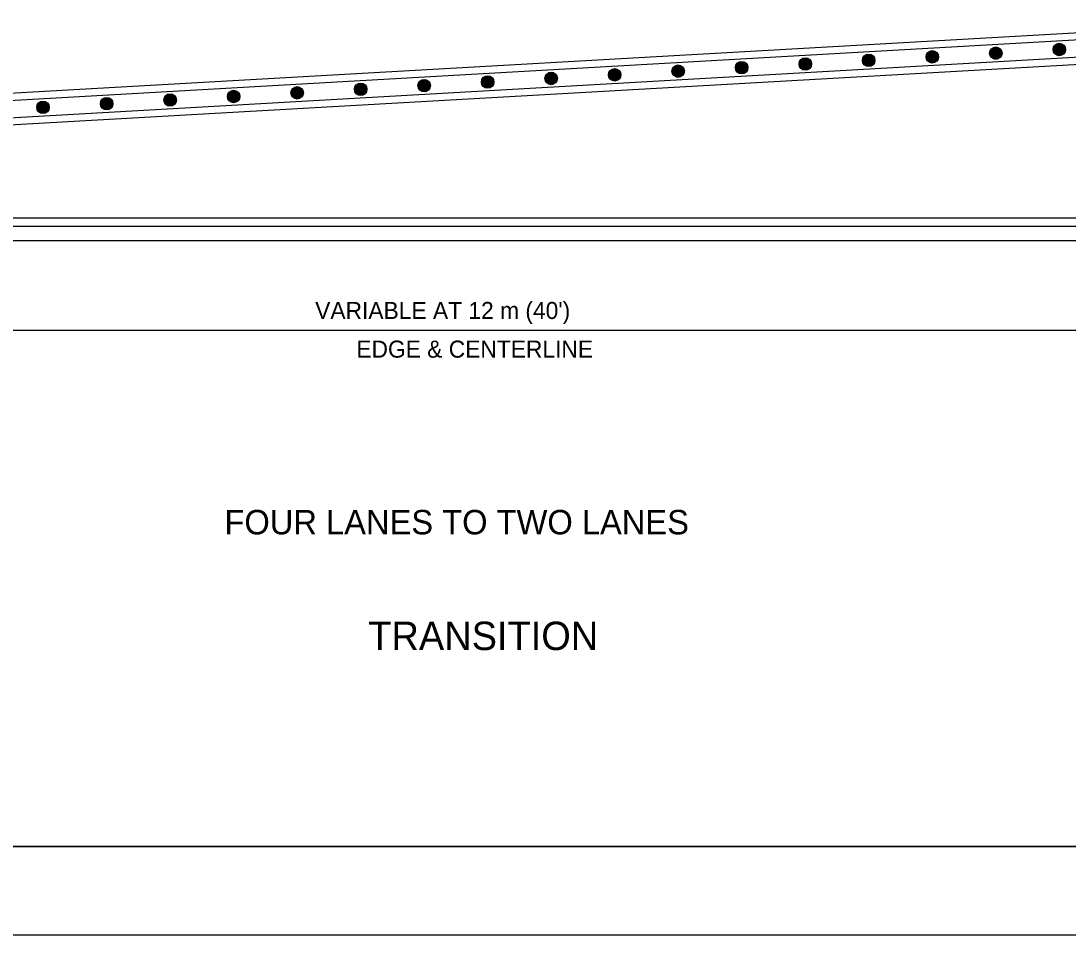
# Model space of a CAD drawing. Extents: x 639362 to 641108, y 298458 to 299646.
# Drawn here: x 639604.4 to 639788.7, y 298457.6 to 298618.5 of the extents above; entities that cross this region are included whole.
import ezdxf

# ---------------------------------------------------------------- set-up
doc = ezdxf.new("R2010")
doc.units = 0
for name, color, linetype in [('1', 7, 'Continuous'), ('2', 7, 'Continuous'), ('PLT-BNDY', 7, 'Continuous')]:
    doc.layers.add(name, color=color, linetype=linetype)

msp = doc.modelspace()

# ---------------------------------------------------------------- linework, layer by layer
at = {"layer": '1'}
for p, q in [((640189.27, 298473.19), (639403.27, 298473.19)), ((639403.27, 298473.19), (639989.27, 298473.19))]:
    msp.add_line(p, q, dxfattribs=at)
at = {"layer": '2'}
for p, q in [((639797.98, 298616.83), (639585.9, 298604.78)), ((639585.93, 298603.58), (639798.02, 298615.63)), ((639797.98, 298612.52), (639585.9, 298600.47)), ((639585.93, 298599.27), (639798.02, 298611.32)), ((639431.63, 298583.85), (639951.12, 298583.85)), ((639431.63, 298582.35), (639951.12, 298582.35)), ((639431.63, 298579.85), (639951.12, 298579.85)), ((639798, 298564.02), (639585.52, 298564.02))]:
    msp.add_line(p, q, dxfattribs=at)
for centre, radius in [((639776.02, 298612.82), 1.1), ((639776.02, 298612.82), 1.02), ((639787.2, 298613.46), 1.1), ((639787.2, 298613.46), 1.02), ((639787.2, 298613.46), 0.946), ((639787.2, 298613.46), 0.868), ((639787.2, 298613.46), 0.789), ((639787.2, 298613.46), 0.711), ((639787.2, 298613.46), 0.633), ((639787.2, 298613.46), 0.554), ((639787.2, 298613.46), 0.476), ((639787.2, 298613.46), 0.398), ((639787.2, 298613.46), 0.32), ((639742.47, 298610.92), 1.1), ((639742.47, 298610.92), 1.02), ((639753.65, 298611.55), 1.1), ((639753.65, 298611.55), 1.02), ((639753.65, 298611.55), 0.946), ((639753.65, 298611.55), 0.868), ((639753.65, 298611.55), 0.789), ((639753.65, 298611.55), 0.711), ((639753.65, 298611.55), 0.633), ((639753.65, 298611.55), 0.554), ((639753.65, 298611.55), 0.476), ((639753.65, 298611.55), 0.398), ((639764.84, 298612.19), 1.1), ((639764.84, 298612.19), 1.02), ((639764.84, 298612.19), 0.946), ((639764.84, 298612.19), 0.868), ((639764.84, 298612.19), 0.789), ((639764.84, 298612.19), 0.711), ((639764.84, 298612.19), 0.633), ((639764.84, 298612.19), 0.554), ((639764.84, 298612.19), 0.476), ((639764.84, 298612.19), 0.398), ((639764.84, 298612.19), 0.32), ((639764.84, 298612.19), 0.241), ((639764.84, 298612.19), 0.163), ((639764.84, 298612.19), 0.0846), ((639776.02, 298612.82), 0.946), ((639776.02, 298612.82), 0.868), ((639776.02, 298612.82), 0.789), ((639776.02, 298612.82), 0.711), ((639776.02, 298612.82), 0.633), ((639776.02, 298612.82), 0.554), ((639776.02, 298612.82), 0.476), ((639776.02, 298612.82), 0.398), ((639776.02, 298612.82), 0.32), ((639776.02, 298612.82), 0.241), ((639776.02, 298612.82), 0.163), ((639776.02, 298612.82), 0.0846), ((639787.2, 298613.46), 0.241), ((639787.2, 298613.46), 0.163), ((639787.2, 298613.46), 0.0846), ((639708.92, 298609.01), 1.1), ((639720.1, 298609.65), 1.1), ((639720.1, 298609.65), 1.02), ((639720.1, 298609.65), 0.946), ((639720.1, 298609.65), 0.868), ((639720.1, 298609.65), 0.789), ((639720.1, 298609.65), 0.711), ((639720.1, 298609.65), 0.633), ((639720.1, 298609.65), 0.554), ((639720.1, 298609.65), 0.476), ((639731.28, 298610.28), 1.1), ((639731.28, 298610.28), 1.02), ((639731.28, 298610.28), 0.946), ((639731.28, 298610.28), 0.868), ((639731.28, 298610.28), 0.789), ((639731.28, 298610.28), 0.711), ((639731.28, 298610.28), 0.633), ((639731.28, 298610.28), 0.554), ((639731.28, 298610.28), 0.476), ((639731.28, 298610.28), 0.398), ((639731.28, 298610.28), 0.32), ((639731.28, 298610.28), 0.241), ((639731.28, 298610.28), 0.163), ((639731.28, 298610.28), 0.0846), ((639742.47, 298610.92), 0.946), ((639742.47, 298610.92), 0.868), ((639742.47, 298610.92), 0.789), ((639742.47, 298610.92), 0.711), ((639742.47, 298610.92), 0.633), ((639742.47, 298610.92), 0.554), ((639742.47, 298610.92), 0.476), ((639742.47, 298610.92), 0.398), ((639742.47, 298610.92), 0.32), ((639742.47, 298610.92), 0.241), ((639742.47, 298610.92), 0.163), ((639742.47, 298610.92), 0.0846), ((639753.65, 298611.55), 0.32), ((639753.65, 298611.55), 0.241), ((639753.65, 298611.55), 0.163), ((639753.65, 298611.55), 0.0846), ((639686.55, 298607.74), 1.1), ((639686.55, 298607.74), 1.02), ((639686.55, 298607.74), 0.946), ((639686.55, 298607.74), 0.868), ((639686.55, 298607.74), 0.789), ((639686.55, 298607.74), 0.711), ((639686.55, 298607.74), 0.633), ((639686.55, 298607.74), 0.554), ((639697.73, 298608.38), 1.1), ((639697.73, 298608.38), 1.02), ((639697.73, 298608.38), 0.946), ((639697.73, 298608.38), 0.868), ((639697.73, 298608.38), 0.789), ((639697.73, 298608.38), 0.711), ((639697.73, 298608.38), 0.633), ((639697.73, 298608.38), 0.554), ((639697.73, 298608.38), 0.476), ((639697.73, 298608.38), 0.398), ((639697.73, 298608.38), 0.32), ((639697.73, 298608.38), 0.241), ((639697.73, 298608.38), 0.163), ((639697.73, 298608.38), 0.0846), ((639708.92, 298609.01), 1.02), ((639708.92, 298609.01), 0.946), ((639708.92, 298609.01), 0.868), ((639708.92, 298609.01), 0.789), ((639708.92, 298609.01), 0.711), ((639708.92, 298609.01), 0.633), ((639708.92, 298609.01), 0.554), ((639708.92, 298609.01), 0.476), ((639708.92, 298609.01), 0.398), ((639708.92, 298609.01), 0.32), ((639708.92, 298609.01), 0.241), ((639708.92, 298609.01), 0.163), ((639708.92, 298609.01), 0.0846), ((639720.1, 298609.65), 0.398), ((639720.1, 298609.65), 0.32), ((639720.1, 298609.65), 0.241), ((639720.1, 298609.65), 0.163), ((639720.1, 298609.65), 0.0846), ((639653, 298605.84), 1.1), ((639653, 298605.84), 1.02), ((639653, 298605.84), 0.946), ((639653, 298605.84), 0.868), ((639653, 298605.84), 0.789), ((639653, 298605.84), 0.711), ((639653, 298605.84), 0.633), ((639664.18, 298606.47), 1.1), ((639664.18, 298606.47), 1.02), ((639664.18, 298606.47), 0.946), ((639664.18, 298606.47), 0.868), ((639664.18, 298606.47), 0.789), ((639664.18, 298606.47), 0.711), ((639664.18, 298606.47), 0.633), ((639664.18, 298606.47), 0.554), ((639664.18, 298606.47), 0.476), ((639664.18, 298606.47), 0.398), ((639664.18, 298606.47), 0.32), ((639664.18, 298606.47), 0.241), ((639664.18, 298606.47), 0.163), ((639664.18, 298606.47), 0.0846), ((639675.37, 298607.11), 1.1), ((639675.37, 298607.11), 1.02), ((639675.37, 298607.11), 0.946), ((639675.37, 298607.11), 0.868), ((639675.37, 298607.11), 0.789), ((639675.37, 298607.11), 0.711), ((639675.37, 298607.11), 0.633), ((639675.37, 298607.11), 0.554), ((639675.37, 298607.11), 0.476), ((639675.37, 298607.11), 0.398), ((639675.37, 298607.11), 0.32), ((639675.37, 298607.11), 0.241), ((639675.37, 298607.11), 0.163), ((639675.37, 298607.11), 0.0846), ((639686.55, 298607.74), 0.476), ((639686.55, 298607.74), 0.398), ((639686.55, 298607.74), 0.32), ((639686.55, 298607.74), 0.241), ((639686.55, 298607.74), 0.163), ((639686.55, 298607.74), 0.0846), ((639619.45, 298603.93), 1.1), ((639619.45, 298603.93), 1.02), ((639619.45, 298603.93), 0.946), ((639619.45, 298603.93), 0.868), ((639619.45, 298603.93), 0.789), ((639619.45, 298603.93), 0.711), ((639619.45, 298603.93), 0.633), ((639630.63, 298604.57), 1.1), ((639630.63, 298604.57), 1.02), ((639630.63, 298604.57), 0.946), ((639630.63, 298604.57), 0.868), ((639630.63, 298604.57), 0.789), ((639630.63, 298604.57), 0.711), ((639630.63, 298604.57), 0.633), ((639630.63, 298604.57), 0.554), ((639630.63, 298604.57), 0.476), ((639630.63, 298604.57), 0.398), ((639630.63, 298604.57), 0.32), ((639630.63, 298604.57), 0.241), ((639630.63, 298604.57), 0.163), ((639630.63, 298604.57), 0.0846), ((639641.81, 298605.2), 1.1), ((639641.81, 298605.2), 1.02), ((639641.81, 298605.2), 0.946), ((639641.81, 298605.2), 0.868), ((639641.81, 298605.2), 0.789), ((639641.81, 298605.2), 0.711), ((639641.81, 298605.2), 0.633), ((639641.81, 298605.2), 0.554), ((639641.81, 298605.2), 0.476), ((639641.81, 298605.2), 0.398), ((639641.81, 298605.2), 0.32), ((639641.81, 298605.2), 0.241), ((639641.81, 298605.2), 0.163), ((639641.81, 298605.2), 0.0846), ((639653, 298605.84), 0.554), ((639653, 298605.84), 0.476), ((639653, 298605.84), 0.398), ((639653, 298605.84), 0.32), ((639653, 298605.84), 0.241), ((639653, 298605.84), 0.163), ((639653, 298605.84), 0.0846), ((639608.26, 298603.3), 1.1), ((639608.26, 298603.3), 1.02), ((639608.26, 298603.3), 0.946), ((639608.26, 298603.3), 0.868), ((639608.26, 298603.3), 0.789), ((639608.26, 298603.3), 0.711), ((639608.26, 298603.3), 0.633), ((639608.26, 298603.3), 0.554), ((639608.26, 298603.3), 0.476), ((639608.26, 298603.3), 0.398), ((639608.26, 298603.3), 0.32), ((639608.26, 298603.3), 0.241), ((639608.26, 298603.3), 0.163), ((639608.26, 298603.3), 0.0846), ((639619.45, 298603.93), 0.554), ((639619.45, 298603.93), 0.476), ((639619.45, 298603.93), 0.398), ((639619.45, 298603.93), 0.32), ((639619.45, 298603.93), 0.241), ((639619.45, 298603.93), 0.163), ((639619.45, 298603.93), 0.0846)]:
    msp.add_circle(centre, radius, dxfattribs=at)
at = {"layer": 'PLT-BNDY'}
msp.add_lwpolyline([(639362.31, 299051.63), (640203.31, 299051.63), (640203.31, 298457.63), (639362.31, 298457.63)], close=True, dxfattribs=at)

# ---------------------------------------------------------------- texts
at = {"layer": '2'}
for s, height, p in [("VARIABLE AT 12 m (40')", 3, (639656.18, 298566.04)), ('EDGE & CENTERLINE', 3, (639663.42, 298559.24)), ('FOUR LANES TO TWO LANES', 4.3, (639640.2, 298528.14)), ('TRANSITION', 5, (639665.53, 298507.78))]:
    msp.add_text(s, height=height, dxfattribs=at).set_placement(p)

doc.saveas('drawing.dxf')
